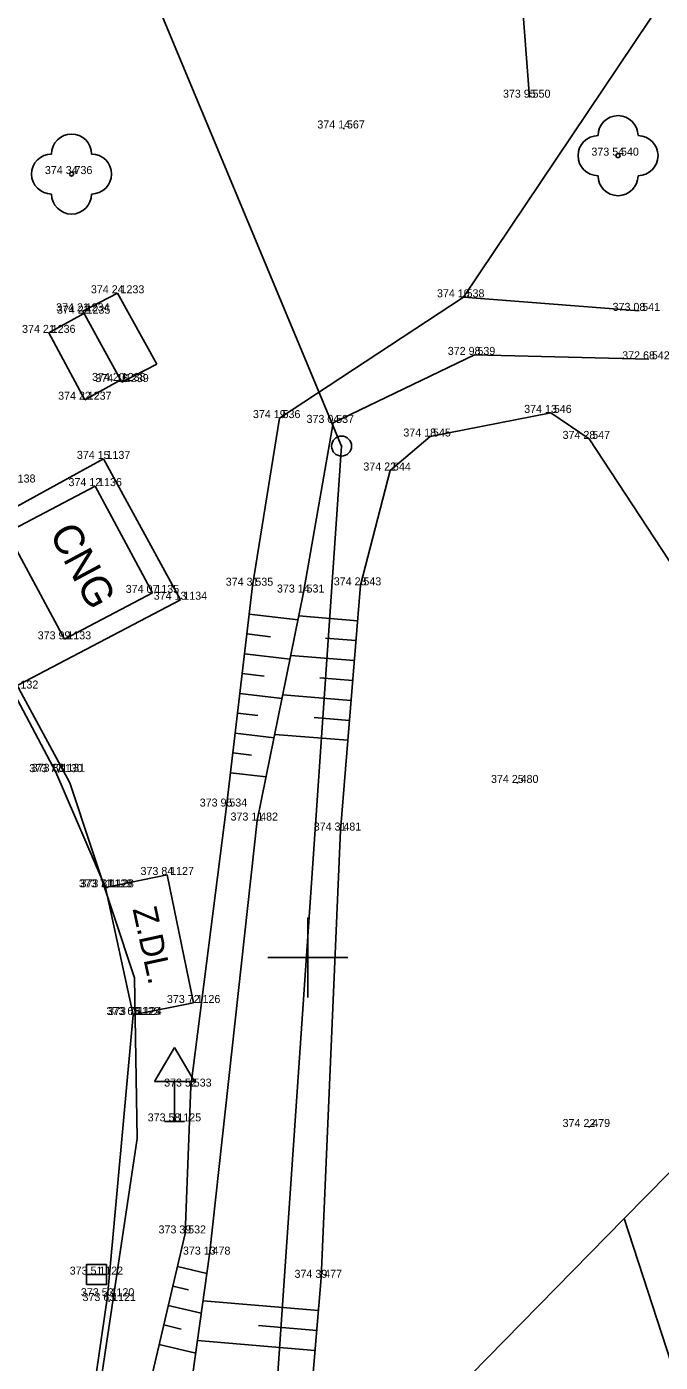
# Model space of a CAD drawing. Extents: x -601196 to -600262, y -1082523 to -1081922.
# Drawn here: x -600507.03 to -600491.19, y -1082160.12 to -1082126.74 of the extents above; entities that cross this region are included whole.
import ezdxf

# ---------------------------------------------------------------- set-up
doc = ezdxf.new("R2010")
doc.units = 0
for name, color, linetype in [('Vrstva 1', 7, 'Continuous'), ('Vrstva 10', 7, 'Continuous'), ('Vrstva 11', 7, 'Continuous'), ('Vrstva 14', 7, 'Continuous'), ('Vrstva 2', 7, 'Continuous'), ('Vrstva 20', 7, 'Continuous'), ('Vrstva 22', 7, 'Continuous'), ('Vrstva 24', 7, 'Continuous'), ('Vrstva 25', 7, 'Continuous'), ('Vrstva 27', 7, 'Continuous'), ('Vrstva 3', 7, 'Continuous'), ('Vrstva 34', 7, 'Continuous'), ('Vrstva 40', 7, 'Continuous'), ('Vrstva 41', 7, 'Continuous'), ('Vrstva 47', 7, 'Continuous'), ('Vrstva 5', 7, 'Continuous'), ('Vrstva 61', 7, 'Continuous'), ('Vrstva 7', 7, 'Continuous')]:
    doc.layers.add(name, color=color, linetype=linetype)

msp = doc.modelspace()

# ---------------------------------------------------------------- linework, layer by layer
at = {"layer": 'Vrstva 1'}
for p, q in [((-600494.46, -1082128.51), (-600494.46, -1082128.51)), ((-600499.1, -1082129.28), (-600499.1, -1082129.28)), ((-600492.25, -1082129.96), (-600492.25, -1082129.96)), ((-600505.91, -1082130.42), (-600505.91, -1082130.42)), ((-600504.76, -1082133.4), (-600504.76, -1082133.4)), ((-600496.11, -1082133.5), (-600496.11, -1082133.5)), ((-600505.63, -1082133.85), (-600505.63, -1082133.85)), ((-600505.61, -1082133.91), (-600505.61, -1082133.91)), ((-600491.72, -1082133.84), (-600491.72, -1082133.84)), ((-600506.48, -1082134.39), (-600506.48, -1082134.39)), ((-600495.84, -1082134.94), (-600495.84, -1082134.94)), ((-600491.48, -1082135.05), (-600491.48, -1082135.05)), ((-600504.73, -1082135.59), (-600504.73, -1082135.59)), ((-600504.65, -1082135.62), (-600504.65, -1082135.62)), ((-600505.58, -1082136.06), (-600505.58, -1082136.06)), ((-600493.93, -1082136.39), (-600493.93, -1082136.39)), ((-600500.71, -1082136.52), (-600500.71, -1082136.52)), ((-600499.37, -1082136.64), (-600499.37, -1082136.64)), ((-600496.95, -1082136.98), (-600496.95, -1082136.98)), ((-600492.97, -1082137.04), (-600492.97, -1082137.04)), ((-600505.11, -1082137.54), (-600505.11, -1082137.54)), ((-600497.95, -1082137.83), (-600497.95, -1082137.83)), ((-600505.32, -1082138.22), (-600505.32, -1082138.22)), ((-600501.39, -1082140.71), (-600501.39, -1082140.71)), ((-600498.69, -1082140.7), (-600498.69, -1082140.7)), ((-600503.89, -1082140.89), (-600503.89, -1082140.89)), ((-600503.19, -1082141.06), (-600503.19, -1082141.06)), ((-600500.11, -1082140.88), (-600500.11, -1082140.88)), ((-600506.09, -1082142.05), (-600506.09, -1082142.05)), ((-600506.3, -1082145.37), (-600506.3, -1082145.37)), ((-600506.24, -1082145.36), (-600506.24, -1082145.36)), ((-600494.76, -1082145.64), (-600494.76, -1082145.64)), ((-600502.04, -1082146.23), (-600502.04, -1082146.23)), ((-600501.27, -1082146.58), (-600501.27, -1082146.58)), ((-600499.19, -1082146.83), (-600499.19, -1082146.83)), ((-600503.52, -1082147.94), (-600503.52, -1082147.94)), ((-600505.06, -1082148.25), (-600505.06, -1082148.25)), ((-600505.02, -1082148.25), (-600505.02, -1082148.25)), ((-600502.86, -1082151.14), (-600502.86, -1082151.14)), ((-600504.37, -1082151.44), (-600504.37, -1082151.44)), ((-600504.33, -1082151.44), (-600504.33, -1082151.44)), ((-600502.93, -1082153.23), (-600502.93, -1082153.23)), ((-600503.34, -1082154.1), (-600503.34, -1082154.1)), ((-600492.97, -1082154.24), (-600492.97, -1082154.24)), ((-600503.07, -1082156.9), (-600503.07, -1082156.9)), ((-600502.46, -1082157.43), (-600502.46, -1082157.43)), ((-600505.29, -1082157.93), (-600505.29, -1082157.93)), ((-600499.67, -1082158.01), (-600499.67, -1082158.01)), ((-600505.01, -1082158.47), (-600505.01, -1082158.47)), ((-600504.97, -1082158.59), (-600504.97, -1082158.59))]:
    msp.add_line(p, q, dxfattribs=at)
at = {"layer": 'Vrstva 10'}
for p, q in [((-600505.6, -1082133.904), (-600506.48, -1082134.39)), ((-600506.48, -1082134.39), (-600505.58, -1082136.06)), ((-600505.58, -1082136.06), (-600504.681, -1082135.563)), ((-600506.3, -1082145.37), (-600507.41, -1082143.28)), ((-600505.06, -1082148.25), (-600506.3, -1082145.37)), ((-600504.37, -1082151.44), (-600505.06, -1082148.25)), ((-600505.01, -1082158.47), (-600504.37, -1082151.44)), ((-600506.43, -1082168.1), (-600505.01, -1082158.47))]:
    msp.add_line(p, q, dxfattribs=at)
at = {"layer": 'Vrstva 11'}
for p, q in [((-600505.11, -1082137.54), (-600509.3, -1082139.84)), ((-600503.19, -1082141.06), (-600505.11, -1082137.54)), ((-600507.41, -1082143.28), (-600503.19, -1082141.06)), ((-600503.52, -1082147.94), (-600505.06, -1082148.25)), ((-600502.86, -1082151.14), (-600503.52, -1082147.94)), ((-600504.37, -1082151.44), (-600502.86, -1082151.14))]:
    msp.add_line(p, q, dxfattribs=at)
at = {"layer": 'Vrstva 14'}
for p, q in [((-600496.11, -1082133.5), (-600490.47, -1082125.09)), ((-600500.71, -1082136.52), (-600496.11, -1082133.5)), ((-600496.11, -1082133.5), (-600491.72, -1082133.84)), ((-600499.37, -1082136.64), (-600495.84, -1082134.94)), ((-600495.84, -1082134.94), (-600491.48, -1082135.05)), ((-600496.95, -1082136.98), (-600493.93, -1082136.39)), ((-600493.93, -1082136.39), (-600492.97, -1082137.04)), ((-600501.39, -1082140.71), (-600500.71, -1082136.52)), ((-600500.11, -1082140.88), (-600499.37, -1082136.64)), ((-600497.95, -1082137.83), (-600496.95, -1082136.98)), ((-600488.22, -1082144.29), (-600492.97, -1082137.04)), ((-600498.69, -1082140.7), (-600497.95, -1082137.83)), ((-600502.04, -1082146.23), (-600501.39, -1082140.71)), ((-600498.69, -1082140.7), (-600499.19, -1082146.83)), ((-600501.27, -1082146.58), (-600500.11, -1082140.88)), ((-600502.93, -1082153.23), (-600502.04, -1082146.23)), ((-600502.46, -1082157.43), (-600501.27, -1082146.58)), ((-600499.67, -1082158.01), (-600499.19, -1082146.83)), ((-600503.07, -1082156.9), (-600502.93, -1082153.23)), ((-600503.52, -1082164.98), (-600502.46, -1082157.43)), ((-600500.44, -1082167.05), (-600499.67, -1082158.01))]:
    msp.add_line(p, q, dxfattribs=at)
msp.add_lwpolyline([(-600503.07, -1082156.9), (-600505.48, -1082167.2), (-600505.47, -1082175.38)], dxfattribs=at)
at = {"layer": 'Vrstva 20'}
for p, q in [((-600499.11, -1082129.28), (-600499.09, -1082129.28)), ((-600499.1, -1082129.265), (-600499.1, -1082129.28)), ((-600499.1, -1082129.295), (-600499.1, -1082129.28)), ((-600506.25, -1082145.36), (-600506.23, -1082145.36)), ((-600506.24, -1082145.345), (-600506.24, -1082145.36)), ((-600506.24, -1082145.375), (-600506.24, -1082145.36)), ((-600494.77, -1082145.64), (-600494.75, -1082145.64)), ((-600494.76, -1082145.625), (-600494.76, -1082145.64)), ((-600494.76, -1082145.655), (-600494.76, -1082145.64)), ((-600505.03, -1082148.25), (-600505.01, -1082148.25)), ((-600505.02, -1082148.235), (-600505.02, -1082148.25)), ((-600505.02, -1082148.265), (-600505.02, -1082148.25)), ((-600504.34, -1082151.44), (-600504.32, -1082151.44)), ((-600504.33, -1082151.425), (-600504.33, -1082151.44)), ((-600504.33, -1082151.455), (-600504.33, -1082151.44)), ((-600492.98, -1082154.24), (-600492.96, -1082154.24)), ((-600492.97, -1082154.225), (-600492.97, -1082154.24)), ((-600492.97, -1082154.255), (-600492.97, -1082154.24)), ((-600504.98, -1082158.59), (-600504.96, -1082158.59)), ((-600504.97, -1082158.575), (-600504.97, -1082158.59)), ((-600504.97, -1082158.605), (-600504.97, -1082158.59))]:
    msp.add_line(p, q, dxfattribs=at)
at = {"layer": 'Vrstva 22'}
for centre in [(-600492.25, -1082129.96), (-600505.91, -1082130.42)]:
    msp.add_circle(centre, 0.05, dxfattribs=at)
for centre, start, end in [((-600492.25, -1082129.46), 0, 180), ((-600505.91, -1082129.92), 0, 180), ((-600492.75, -1082129.96), 90, 270), ((-600491.75, -1082129.96), 270, 90), ((-600506.41, -1082130.42), 90, 270), ((-600505.41, -1082130.42), 270, 90), ((-600492.25, -1082130.46), 180, 0), ((-600505.91, -1082130.92), 180, 0)]:
    msp.add_arc(centre, 0.5, start, end, dxfattribs=at)
at = {"layer": 'Vrstva 24'}
for p, q in [((-600504.76, -1082133.4), (-600505.63, -1082133.85)), ((-600504.76, -1082133.4), (-600503.78, -1082135.17)), ((-600505.63, -1082133.85), (-600504.65, -1082135.62)), ((-600504.65, -1082135.62), (-600503.78, -1082135.17))]:
    msp.add_line(p, q, dxfattribs=at)
at = {"layer": 'Vrstva 25'}
for p, q in [((-600501.474, -1082141.421), (-600500.249, -1082141.565)), ((-600498.762, -1082141.584), (-600500.229, -1082141.465)), ((-600501.532, -1082141.916), (-600500.941, -1082141.986)), ((-600498.803, -1082142.083), (-600499.566, -1082142.02)), ((-600501.59, -1082142.412), (-600500.449, -1082142.546)), ((-600498.843, -1082142.581), (-600500.43, -1082142.452)), ((-600501.649, -1082142.907), (-600501.099, -1082142.972)), ((-600498.884, -1082143.079), (-600499.707, -1082143.012)), ((-600501.707, -1082143.403), (-600500.649, -1082143.527)), ((-600498.925, -1082143.578), (-600500.631, -1082143.438)), ((-600501.765, -1082143.898), (-600501.257, -1082143.958)), ((-600498.965, -1082144.076), (-600499.848, -1082144.004)), ((-600501.824, -1082144.394), (-600500.848, -1082144.509)), ((-600499.006, -1082144.574), (-600500.831, -1082144.425)), ((-600501.882, -1082144.889), (-600501.415, -1082144.944)), ((-600501.94, -1082145.385), (-600501.048, -1082145.49)), ((-600503.264, -1082157.729), (-600502.526, -1082157.902)), ((-600503.378, -1082158.216), (-600502.987, -1082158.307)), ((-600503.492, -1082158.703), (-600502.666, -1082158.896)), ((-600499.74, -1082158.831), (-600502.622, -1082158.585)), ((-600503.606, -1082159.189), (-600503.171, -1082159.291)), ((-600499.782, -1082159.329), (-600501.237, -1082159.205)), ((-600503.72, -1082159.676), (-600502.805, -1082159.89)), ((-600499.825, -1082159.827), (-600502.761, -1082159.577))]:
    msp.add_line(p, q, dxfattribs=at)
at = {"layer": 'Vrstva 27'}
msp.add_line((-600505.54, -1082157.93), (-600505.04, -1082157.93), dxfattribs=at)
msp.add_lwpolyline([(-600505.54, -1082158.18), (-600505.04, -1082158.18), (-600505.04, -1082157.68), (-600505.54, -1082157.68)], close=True, dxfattribs=at)
at = {"layer": 'Vrstva 34'}
for p, q in [((-600503.84, -1082153.1), (-600503.34, -1082152.25)), ((-600503.34, -1082152.25), (-600502.84, -1082153.1)), ((-600503.84, -1082153.1), (-600502.84, -1082153.1)), ((-600503.34, -1082154.1), (-600503.34, -1082153.1)), ((-600503.59, -1082154.1), (-600503.09, -1082154.1))]:
    msp.add_line(p, q, dxfattribs=at)
at = {"layer": 'Vrstva 47'}
for p, q in [((-600499.16, -1082137.22), (-600514.89, -1082099.5)), ((-600492.1, -1082156.53), (-600460.95, -1082124.84)), ((-600515.03, -1082128.91), (-600505.95, -1082145.64)), ((-600501.12, -1082165.71), (-600499.16, -1082137.22)), ((-600505.95, -1082145.64), (-600504.34, -1082150.51)), ((-600504.34, -1082150.51), (-600504.27, -1082154.53)), ((-600504.27, -1082154.53), (-600506.06, -1082166.47)), ((-600501.12, -1082165.71), (-600492.1, -1082156.53)), ((-600492.1, -1082156.53), (-600484.44, -1082179.95))]:
    msp.add_line(p, q, dxfattribs=at)
for radius in [0.25, 0.005]:
    msp.add_circle((-600499.16, -1082137.22), radius, dxfattribs=at)
at = {"layer": 'Vrstva 5'}
for p, q in [((-600505.32, -1082138.22), (-600507.52, -1082139.38)), ((-600503.89, -1082140.89), (-600505.32, -1082138.22)), ((-600506.09, -1082142.05), (-600507.52, -1082139.38)), ((-600506.09, -1082142.05), (-600503.89, -1082140.89))]:
    msp.add_line(p, q, dxfattribs=at)
at = {"layer": 'Vrstva 61'}
for p, q in [((-600500, -1082149), (-600500, -1082151)), ((-600500, -1082149), (-600500, -1082151)), ((-600501, -1082150), (-600499, -1082150)), ((-600501, -1082150), (-600499, -1082150))]:
    msp.add_line(p, q, dxfattribs=at)
at = {"layer": 'Vrstva 7'}
msp.add_line((-600494.46, -1082128.51), (-600494.72, -1082125.09), dxfattribs=at)

# ---------------------------------------------------------------- texts
at = {"layer": 'Vrstva 2'}
for s, p in [(' 550', (-600494.46, -1082128.51)), (' 567', (-600499.1, -1082129.28)), (' 540', (-600492.25, -1082129.96)), (' 736', (-600505.91, -1082130.42)), (' 1233', (-600504.76, -1082133.4)), (' 538', (-600496.11, -1082133.5)), (' 1234', (-600505.63, -1082133.85)), (' 1235', (-600505.61, -1082133.91)), (' 541', (-600491.72, -1082133.84)), (' 1236', (-600506.48, -1082134.39)), (' 539', (-600495.84, -1082134.94)), (' 542', (-600491.48, -1082135.05)), (' 1238', (-600504.73, -1082135.59)), (' 1239', (-600504.65, -1082135.62)), (' 1237', (-600505.58, -1082136.06)), (' 536', (-600500.71, -1082136.52)), (' 537', (-600499.37, -1082136.64)), (' 546', (-600493.93, -1082136.39)), (' 545', (-600496.95, -1082136.98)), (' 547', (-600492.97, -1082137.04)), (' 1137', (-600505.11, -1082137.54)), (' 544', (-600497.95, -1082137.83)), (' 1138', (-600507.48, -1082138.13)), (' 1136', (-600505.32, -1082138.22)), (' 535', (-600501.39, -1082140.71)), (' 543', (-600498.69, -1082140.7)), (' 1135', (-600503.89, -1082140.89)), (' 531', (-600500.11, -1082140.88)), (' 1134', (-600503.19, -1082141.06)), (' 1133', (-600506.09, -1082142.05)), (' 1132', (-600507.41, -1082143.28)), (' 1130', (-600506.3, -1082145.37)), (' 1131', (-600506.24, -1082145.36)), (' 480', (-600494.76, -1082145.64)), (' 534', (-600502.04, -1082146.23)), (' 482', (-600501.27, -1082146.58)), (' 481', (-600499.19, -1082146.83)), (' 1127', (-600503.52, -1082147.94)), (' 1129', (-600505.06, -1082148.25)), (' 1128', (-600505.02, -1082148.25)), (' 1126', (-600502.86, -1082151.14)), (' 1123', (-600504.37, -1082151.44)), (' 1124', (-600504.33, -1082151.44)), (' 533', (-600502.93, -1082153.23)), (' 1125', (-600503.34, -1082154.1)), (' 479', (-600492.97, -1082154.24)), (' 532', (-600503.07, -1082156.9)), (' 478', (-600502.46, -1082157.43)), (' 1122', (-600505.29, -1082157.93)), (' 477', (-600499.67, -1082158.01)), (' 1120', (-600505.01, -1082158.47)), (' 1121', (-600504.97, -1082158.59))]:
    msp.add_text(s, height=0.2, dxfattribs=at).set_placement(p)
at = {"layer": 'Vrstva 3'}
for s, p in [('373 95 ', (-600495.126, -1082128.51)), ('374 14 ', (-600499.766, -1082129.28)), ('373 54 ', (-600492.916, -1082129.96)), ('374 34 ', (-600506.576, -1082130.42)), ('374 24 ', (-600505.426, -1082133.4)), ('374 10 ', (-600496.776, -1082133.5)), ('374 21 ', (-600506.296, -1082133.85)), ('374 22 ', (-600506.276, -1082133.91)), ('373 08 ', (-600492.386, -1082133.84)), ('374 21 ', (-600507.146, -1082134.39)), ('372 98 ', (-600496.506, -1082134.94)), ('372 68 ', (-600492.146, -1082135.05)), ('374 20 ', (-600505.396, -1082135.59)), ('374 16 ', (-600505.316, -1082135.62)), ('374 22 ', (-600506.246, -1082136.06)), ('374 19 ', (-600501.376, -1082136.52)), ('373 04 ', (-600500.036, -1082136.64)), ('374 13 ', (-600494.596, -1082136.39)), ('374 18 ', (-600497.616, -1082136.98)), ('374 28 ', (-600493.636, -1082137.04)), ('374 15 ', (-600505.776, -1082137.54)), ('374 22 ', (-600498.616, -1082137.83)), ('374 12 ', (-600505.986, -1082138.22)), ('374 31 ', (-600502.056, -1082140.71)), ('374 23 ', (-600499.356, -1082140.7)), ('374 07 ', (-600504.556, -1082140.89)), ('373 14 ', (-600500.776, -1082140.88)), ('374 13 ', (-600503.856, -1082141.06)), ('373 99 ', (-600506.756, -1082142.05)), ('373 77 ', (-600506.966, -1082145.37)), ('373 88 ', (-600506.906, -1082145.36)), ('374 25 ', (-600495.426, -1082145.64)), ('373 95 ', (-600502.706, -1082146.23)), ('373 11 ', (-600501.936, -1082146.58)), ('374 31 ', (-600499.856, -1082146.83)), ('373 84 ', (-600504.186, -1082147.94)), ('373 71 ', (-600505.726, -1082148.25)), ('373 81 ', (-600505.686, -1082148.25)), ('373 72 ', (-600503.526, -1082151.14)), ('373 65 ', (-600505.036, -1082151.44)), ('373 76 ', (-600504.996, -1082151.44)), ('373 52 ', (-600503.596, -1082153.23)), ('373 58 ', (-600504.006, -1082154.1)), ('374 22 ', (-600493.636, -1082154.24)), ('373 39 ', (-600503.736, -1082156.9)), ('373 13 ', (-600503.126, -1082157.43)), ('373 51 ', (-600505.956, -1082157.93)), ('374 39 ', (-600500.336, -1082158.01)), ('373 53 ', (-600505.676, -1082158.47)), ('373 63 ', (-600505.636, -1082158.59))]:
    msp.add_text(s, height=0.2, dxfattribs=at).set_placement(p)
at = {"layer": 'Vrstva 40'}
msp.add_text('Z.DL.', height=0.6, rotation=282.2051, dxfattribs=at).set_placement((-600504.386, -1082148.792))
at = {"layer": 'Vrstva 41'}
msp.add_text('CNG', height=0.75, rotation=298.1726, dxfattribs=at).set_placement((-600506.478, -1082139.4))

doc.saveas('drawing.dxf')
